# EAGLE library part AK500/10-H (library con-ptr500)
CONNECTOR Aug. 2004 / PTR Meßtechnik: Die Bezeichnung der Serie AK505 wurde geändert. Es handelt sich hierbei um AK500 in horizontaler Ausführung.
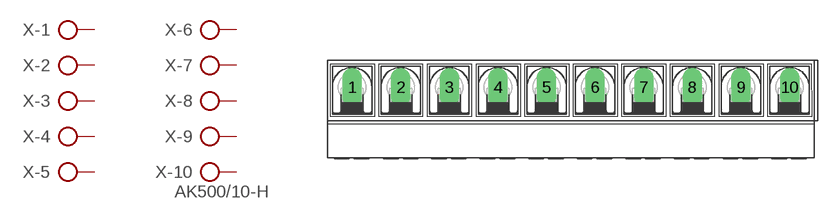
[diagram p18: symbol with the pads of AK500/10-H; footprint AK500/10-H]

Designator prefix X; gates -1=KL -2=KL -3=KL -4=KL -5=KL -6=KL -7=KL -8=KL -9=KL -10=KLV

## AK500/10-H (OC_FARNELL: unknown; OC_NEWARK: unknown)  [AK500/10-H]
1  -1:KL  pas
2  -2:KL  pas
3  -3:KL  pas
4  -4:KL  pas
5  -5:KL  pas
6  -6:KL  pas
7  -7:KL  pas
8  -8:KL  pas
9  -9:KL  pas
10  -10:KL  pas

## Footprint AK500/10-H (pad centres in mm)
CONNECTOR Aug. 2004 / PTR Meßtechnik: Die Bezeichnung der Serie AK505 wurde geändert. Es handelt sich hierbei um AK500 in horizontaler Ausführung.
drill 1.321 long: 1 -22.504,0; 2 -17.501,0; 3 -12.497,0; 4 -7.493,0; 5 -2.489,0; 6 2.489,0; 7 7.493,0; 8 12.497,0; 9 17.501,0; 10 22.504,0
